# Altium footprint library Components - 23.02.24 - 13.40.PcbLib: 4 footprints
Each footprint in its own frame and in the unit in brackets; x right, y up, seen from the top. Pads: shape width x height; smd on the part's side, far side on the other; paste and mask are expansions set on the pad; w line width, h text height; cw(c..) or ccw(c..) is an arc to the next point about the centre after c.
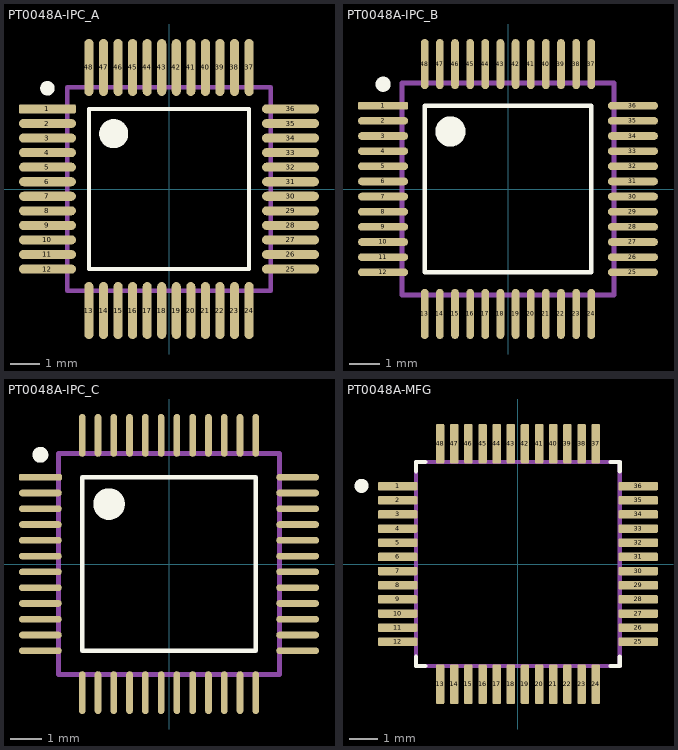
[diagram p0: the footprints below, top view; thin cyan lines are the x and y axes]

## PT0048A-IPC_A [mm]
pads (48):
  rrect32% 1.955x0.312 smd paste+0 mask+0: 1(-4.175,2.75)
  rrect100% 1.955x0.312 smd paste+0 mask+0: 2(-4.175,2.25) 3(-4.175,1.75) 4(-4.175,1.25) 5(-4.175,0.75) 6(-4.175,0.25) 7(-4.175,-0.25) 8(-4.175,-0.75) 9(-4.175,-1.25) 10(-4.175,-1.75) 11(-4.175,-2.25) 12(-4.175,-2.75) 25(4.175,-2.75) 26(4.175,-2.25) 27(4.175,-1.75) 28(4.175,-1.25) 29(4.175,-0.75) 30(4.175,-0.25) 31(4.175,0.25) 32(4.175,0.75) 33(4.175,1.25) 34(4.175,1.75) 35(4.175,2.25) 36(4.175,2.75)
  rrect100% 0.312x1.955 smd paste+0 mask+0: 13(-2.75,-4.175) 14(-2.25,-4.175) 15(-1.75,-4.175) 16(-1.25,-4.175) 17(-0.75,-4.175) 18(-0.25,-4.175) 19(0.25,-4.175) 20(0.75,-4.175) 21(1.25,-4.175) 22(1.75,-4.175) 23(2.25,-4.175) 24(2.75,-4.175) 37(2.75,4.175) 38(2.25,4.175) 39(1.75,4.175) 40(1.25,4.175) 41(0.75,4.175) 42(0.25,4.175) 43(-0.25,4.175) 44(-0.75,4.175) 45(-1.25,4.175) 46(-1.75,4.175) 47(-2.25,4.175) 48(-2.75,4.175)
Top Overlay:
  circle w0.25: c-4.175,3.46 r0.125
  circle w0.5: c-1.9,1.9 r0.25
  lines w0.15: -2.75,-2.75 2.75,-2.75 2.75,2.75 -2.75,2.75 -2.75,-2.75
Mechanical 5:
  lines w0.15: -3.5,-3.5 3.5,-3.5 3.5,3.5 -3.5,3.5 -3.5,-3.5
  text ".Designator" at 0.05,0.217 h0.5
3D body "IC_MSPM0G1507SPT_PQFP48.STEP": height 0.25, standoff 0, extent -5.653,-5.653 5.653,5.653

## PT0048A-IPC_B [mm]
pads (48):
  rrect40% 1.655x0.252 smd paste+0 mask+0: 1(-4.125,2.75)
  rrect100% 1.655x0.252 smd paste+0 mask+0: 2(-4.125,2.25) 3(-4.125,1.75) 4(-4.125,1.25) 5(-4.125,0.75) 6(-4.125,0.25) 7(-4.125,-0.25) 8(-4.125,-0.75) 9(-4.125,-1.25) 10(-4.125,-1.75) 11(-4.125,-2.25) 12(-4.125,-2.75) 25(4.125,-2.75) 26(4.125,-2.25) 27(4.125,-1.75) 28(4.125,-1.25) 29(4.125,-0.75) 30(4.125,-0.25) 31(4.125,0.25) 32(4.125,0.75) 33(4.125,1.25) 34(4.125,1.75) 35(4.125,2.25) 36(4.125,2.75)
  rrect100% 0.252x1.655 smd paste+0 mask+0: 13(-2.75,-4.125) 14(-2.25,-4.125) 15(-1.75,-4.125) 16(-1.25,-4.125) 17(-0.75,-4.125) 18(-0.25,-4.125) 19(0.25,-4.125) 20(0.75,-4.125) 21(1.25,-4.125) 22(1.75,-4.125) 23(2.25,-4.125) 24(2.75,-4.125) 37(2.75,4.125) 38(2.25,4.125) 39(1.75,4.125) 40(1.25,4.125) 41(0.75,4.125) 42(0.25,4.125) 43(-0.25,4.125) 44(-0.75,4.125) 45(-1.25,4.125) 46(-1.75,4.125) 47(-2.25,4.125) 48(-2.75,4.125)
Top Overlay:
  circle w0.25: c-4.125,3.46 r0.125
  circle w0.5: c-1.9,1.9 r0.25
  lines w0.15: -2.75,-2.75 2.75,-2.75 2.75,2.75 -2.75,2.75 -2.75,-2.75
Mechanical 5:
  lines w0.15: -3.5,-3.5 3.5,-3.5 3.5,3.5 -3.5,3.5 -3.5,-3.5
  text ".Designator" at 0.05,0.217 h0.5
3D body "IC_MSPM0G1507SPT_PQFP48.STEP": height 0.25, standoff 0, extent -5.203,-5.203 5.203,5.203

## PT0048A-IPC_C [mm]
pads (48):
  rrect47% 1.355x0.212 smd paste+0 mask+0: 1(-4.075,2.75)
  rrect100% 1.355x0.212 smd paste+0 mask+0: 2(-4.075,2.25) 3(-4.075,1.75) 4(-4.075,1.25) 5(-4.075,0.75) 6(-4.075,0.25) 7(-4.075,-0.25) 8(-4.075,-0.75) 9(-4.075,-1.25) 10(-4.075,-1.75) 11(-4.075,-2.25) 12(-4.075,-2.75) 25(4.075,-2.75) 26(4.075,-2.25) 27(4.075,-1.75) 28(4.075,-1.25) 29(4.075,-0.75) 30(4.075,-0.25) 31(4.075,0.25) 32(4.075,0.75) 33(4.075,1.25) 34(4.075,1.75) 35(4.075,2.25) 36(4.075,2.75)
  rrect100% 0.212x1.355 smd paste+0 mask+0: 13(-2.75,-4.075) 14(-2.25,-4.075) 15(-1.75,-4.075) 16(-1.25,-4.075) 17(-0.75,-4.075) 18(-0.25,-4.075) 19(0.25,-4.075) 20(0.75,-4.075) 21(1.25,-4.075) 22(1.75,-4.075) 23(2.25,-4.075) 24(2.75,-4.075) 37(2.75,4.075) 38(2.25,4.075) 39(1.75,4.075) 40(1.25,4.075) 41(0.75,4.075) 42(0.25,4.075) 43(-0.25,4.075) 44(-0.75,4.075) 45(-1.25,4.075) 46(-1.75,4.075) 47(-2.25,4.075) 48(-2.75,4.075)
Top Overlay:
  circle w0.25: c-4.075,3.46 r0.125
  circle w0.5: c-1.9,1.9 r0.25
  lines w0.15: -2.75,-2.75 2.75,-2.75 2.75,2.75 -2.75,2.75 -2.75,-2.75
Mechanical 5:
  lines w0.15: -3.5,-3.5 3.5,-3.5 3.5,3.5 -3.5,3.5 -3.5,-3.5
  text ".Designator" at 0.05,0.217 h0.5
3D body "IC_MSPM0G1507SPT_PQFP48.STEP": height 0.25, standoff 0, extent -4.853,-4.853 4.853,4.853

## PT0048A-MFG [mm]
pads (48):
  rrect33% 1.4x0.3 smd paste-1000 mask+0: 1(-4.25,2.75) 2(-4.25,2.25) 3(-4.25,1.75) 4(-4.25,1.25) 5(-4.25,0.75) 6(-4.25,0.25) 7(-4.25,-0.25) 8(-4.25,-0.75) 9(-4.25,-1.25) 10(-4.25,-1.75) 11(-4.25,-2.25) 12(-4.25,-2.75) 25(4.25,-2.75) 26(4.25,-2.25) 27(4.25,-1.75) 28(4.25,-1.25) 29(4.25,-0.75) 30(4.25,-0.25) 31(4.25,0.25) 32(4.25,0.75) 33(4.25,1.25) 34(4.25,1.75) 35(4.25,2.25) 36(4.25,2.75)
  rrect33% 0.3x1.4 smd paste-1000 mask+0: 13(-2.75,-4.25) 14(-2.25,-4.25) 15(-1.75,-4.25) 16(-1.25,-4.25) 17(-0.75,-4.25) 18(-0.25,-4.25) 19(0.25,-4.25) 20(0.75,-4.25) 21(1.25,-4.25) 22(1.75,-4.25) 23(2.25,-4.25) 24(2.75,-4.25) 37(2.75,4.25) 38(2.25,4.25) 39(1.75,4.25) 40(1.25,4.25) 41(0.75,4.25) 42(0.25,4.25) 43(-0.25,4.25) 44(-0.75,4.25) 45(-1.25,4.25) 46(-1.75,4.25) 47(-2.25,4.25) 48(-2.75,4.25)
Top Overlay:
  circle w0.25: c-5.525,2.76 r0.125
  lines w0.15: -3.6,-3.275 -3.6,-3.6 -3.275,-3.6 ; -3.6,3.275 -3.6,3.6 -3.275,3.6 ; 3.275,-3.6 3.6,-3.6 3.6,-3.275 ; 3.275,3.6 3.6,3.6 3.6,3.275
Top Paste:
  drawing of 48 lines, arcs and shapes, not listed
Mechanical 5:
  lines w0.15: -3.6,-3.6 3.6,-3.6 3.6,3.6 -3.6,3.6 -3.6,-3.6
  text ".Designator" at 0,0 h0.5
3D body "IC_MSPM0G1507SPT_PQFP48.STEP": height 0.25, standoff 0, extent -5.05,-5.05 5.05,5.05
